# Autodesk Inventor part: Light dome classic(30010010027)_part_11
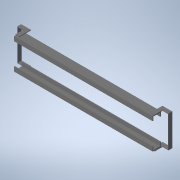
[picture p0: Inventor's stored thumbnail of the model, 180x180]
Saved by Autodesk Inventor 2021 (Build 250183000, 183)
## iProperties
Created: 2026-04
Part Number: Light dome classic(30010010027)_part_11
Material: Generic
Catalog Web Link: www.3dfindit.com
Description: Light dome classic_part_11-
Vendor: KINGSPAN
Document SubType Name: Modeling
Designer: psAdmin
Manufacturer: KINGSPAN
Mass: 514.912 g
Surface Area: 2764.56 cm^2
Volume: 514.912 cm^3
Density: 1 g/cm^3
Appearance: PSOLRGB-255-255-255
Category: PARTsolutions
Company: KINGSPAN
Title: Light dome classic(30010010027)_part_11
Author: Cadenas PARTsolutions
PSOL_IDENT_0: {$CADENAS_DATA/23d-libs/kingspan_kla/light_dome_classic/parts/part_11.prj},257 {VTYP=3D},{NB=Light d
PSOL_IDENT_1: ome classic(30010010027)_part_11},{LINA=Light dome classic(30010010027)_part_11},{NN=Light dome clas
PSOL_IDENT_2: sic_part_11},{DATE=15.07.2024 10:56:11},{GEOMDATE=03.07.2024 08:28:24},{VERSION=},{LINEID=10},{WBVAR=
PSOL_IDENT_3: LODLEVEL,L,W,DP,OP},{WBNUMERIC=W}  {NB=Light dome classic(30010010027)_part_11},{LINA=Light dome cla
PSOL_IDENT_4: ssic(30010010027)_part_11},{KT=DUMMY},{IDNR=},{PN=Light dome classic},{LODLEVEL=300},{L=100},{W=100}
PSOL_IDENT_5: ,{DRIVE=1},{WX=100,150,200,250,300},{DP=2},{OP=7},{OPX='7','24/48 V OPEN/CLOSE including ventilation
PSOL_IDENT_6: function'},{LX=1000},{XWX=1000},{VER=3},{DPX='1', 'Natural ventilation', '2'  , 'NSHEV (natural smo
PSOL_IDENT_7: ke, heat exhaust ventilation)', '3', 'Fixed','4','NSHE'}
NB: Light dome classic(30010010027)_part_11
NN: Light dome classic_part_11
NBSYN: $PN.($LODLEVEL.$L.$W.$DP.$OP.)_part_11
LINA: Light dome classic(30010010027)_part_11
CATALOG: Light + Air
PN: Light dome classic
LODLEVEL: 300
L: 100
W: 100
DP: NSHEV (natural smoke, heat exhaust ventilation)
OP: 24/48 V OPEN/CLOSE including ventilation function
SUPPLIER: KINGSPAN
ARTICLENO: Light dome classic(30010010027)_part_11
BOMINFO: Light dome classic(30010010027)_part_11
CREATOR: CADENAS GmbH
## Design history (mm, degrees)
sketch "Sketch_1"
  geometry: L1 (-394, -83)-(-343, -83); L2 (-343, -83)-(-343, -80); L3 (-343, -80)-(-391, -80); L4 (-391, -80)-(-391, 80); L5 (-391, 80)-(-343, 80); L6 (-343, 80)-(-343, 83); L7 (-343, 83)-(-394, 83); L8 (-394, 83)-(-394, -83)
  constraints: 16 end point
extrude "Extrusion1" join sketch "Sketch_1" distance "d0" = 61; taper "d1" = 0 deg
sketch "Sketch_2"
  geometry: L1 (-15, -20)-(85, -20); L2 (85, -20)-(85, 80); L3 (85, 80)-(-15, 80); L4 (-15, 80)-(-15, -20); L5 (0, 20)-(0, 0); L6 (0, 0)-(51, 0); L7 (51, 0)-(51, 61); L8 (51, 61)-(31, 61); L9 (31, 61)-(31, 20); L10 (31, 20)-(0, 20)
  constraints: 20 end point
extrude "Extrusion2" cut sketch "Sketch_2" distance "d2" = 166; taper "d3" = 0 deg
sketch "Sketch_3"
  geometry: L1 (-57, 69.5)-(-80, 69.5); L2 (-80, 69.5)-(-80, 25.5); L3 (-80, 25.5)-(-57, 25.5); L4 (-57, 25.5)-(-57, 29.5); L5 (-57, 29.5)-(-76, 29.5); L6 (-76, 29.5)-(-76, 65.5); L7 (-76, 65.5)-(-57, 65.5); L8 (-57, 65.5)-(-57, 69.5)
  constraints: 16 end point
extrude "Extrusion3" join sketch "Sketch_3" stored distance "d4" = 722; taper "d5" = 0 deg
sketch "Sketch_5"
  geometry: L1 (343, -80)-(343, -83); L2 (343, -83)-(394, -83); L3 (394, -83)-(394, 83); L4 (394, 83)-(343, 83); L5 (343, 83)-(343, 80); L6 (343, 80)-(391, 80); L7 (391, 80)-(391, -80); L8 (391, -80)-(343, -80)
  constraints: 16 end point
extrude "Extrusion4" join sketch "Sketch_5" distance "d6" = 61; taper "d7" = 0 deg
sketch "Sketch_6"
  geometry: L1 (309, 20)-(309, -80); L2 (309, -80)-(409, -80); L3 (409, -80)-(409, 20); L4 (409, 20)-(309, 20); L5 (343, -61)-(363, -61); L6 (363, -61)-(363, -20); L7 (363, -20)-(394, -20); L8 (394, -20)-(394, 0); L9 (394, 0)-(343, 0); L10 (343, 0)-(343, -61)
  constraints: 20 end point
extrude "Extrusion5" cut sketch "Sketch_6" distance "d8" = 3; taper "d9" = 0 deg
sketch "Sketch_7"
  geometry: L1 (309, 20)-(309, -80); L2 (309, -80)-(409, -80); L3 (409, -80)-(409, 20); L4 (409, 20)-(309, 20); L5 (343, -61)-(363, -61); L6 (363, -61)-(363, -20); L7 (363, -20)-(394, -20); L8 (394, -20)-(394, 0); L9 (394, 0)-(343, 0); L10 (343, 0)-(343, -61)
  constraints: 20 end point
extrude "Extrusion6" cut sketch "Sketch_7" distance "d10" = 3; taper "d11" = 0 deg
sketch "Sketch_8"
  geometry: L1 (-50, 166)-(-50, 0); L2 (-50, 0)-(0, 0); L3 (0, 0)-(0, 166); L4 (0, 166)-(-50, 166)
  constraints: 8 end point
extrude "Extrusion7" cut sketch "Sketch_8" distance "d12" = 3; taper "d13" = 0 deg
sketch "Sketch_4"
  geometry: L1 (57, 69.5)-(57, 65.5); L2 (57, 65.5)-(76, 65.5); L3 (76, 65.5)-(76, 29.5); L4 (76, 29.5)-(57, 29.5); L5 (57, 29.5)-(57, 25.5); L6 (57, 25.5)-(80, 25.5); L7 (80, 25.5)-(80, 69.5); L8 (80, 69.5)-(57, 69.5)
  constraints: 16 end point
extrude "Extrusion8" join sketch "Sketch_4" stored distance "d14" = 722; taper "d15" = 0 deg
node "IP_11_XY"
node "IP_11_YZ"
node "IP_11_ZX"
node "IP_11_X"
node "IP_11_Y"
node "IP_11_Z"
node "IP_11_Center"
body "Solid1"
